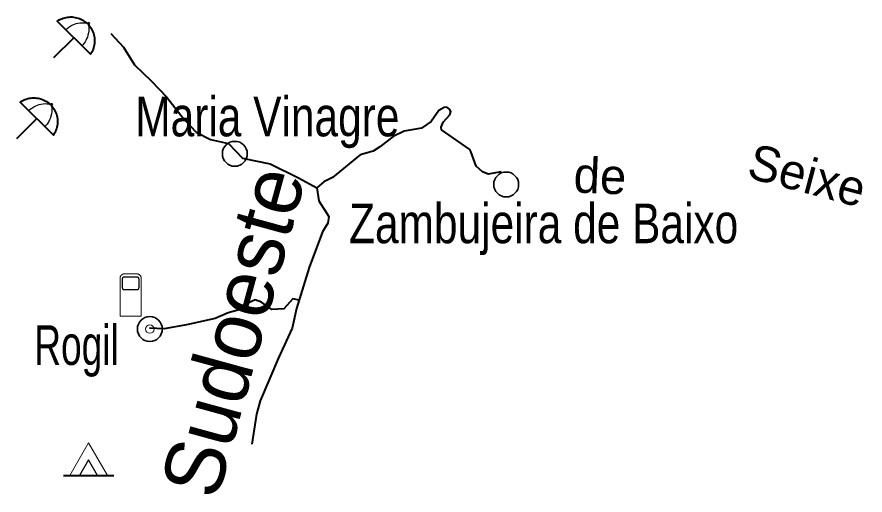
# Model space of a CAD drawing. Extents: x 515362 to 530328, y 4133002 to 4141437.
import ezdxf

# ---------------------------------------------------------------- set-up
doc = ezdxf.new("R2010")
doc.units = 0
doc.header["$LTSCALE"] = 280
for name, color, linetype in [('13', 7, 'Continuous'), ('14', 7, 'Continuous'), ('49', 7, 'Continuous'), ('59', 7, 'Continuous')]:
    doc.layers.add(name, color=color, linetype=linetype)
for name, color, linetype, lineweight in [('17', 7, 'Continuous', 35), ('23', 7, 'Continuous', 40), ('27', 7, 'Continuous', 13), ('57', 7, 'Continuous', 40)]:
    doc.layers.add(name, color=color, linetype=linetype, lineweight=lineweight)

msp = doc.modelspace()

# ---------------------------------------------------------------- linework, layer by layer
at = {"layer": '17'}
for centre in [(519206.5, 4139022.7), (523995.3, 4138481.4), (517706.9, 4135930.7)]:
    msp.add_circle(centre, 220, dxfattribs=at)
at = {"layer": '17', "lineweight": 13}
msp.add_circle((517706.9, 4135930.7), 75, dxfattribs=at)
at = {"layer": '23'}
for points in [[(517017.7, 4141142.4), (517244.1, 4140902.4), (517439.1, 4140592.9), (517738.5, 4140304.7), (518000.5, 4140029), (518319.4, 4139624), (518525.4, 4139403.4), (518776.8, 4139275.9), (519092.7, 4139204.6), (519343.5, 4138942.9), (519829.1, 4138844.6), (520332.8, 4138598.9), (520653.5, 4138424.5)], [(523905.1, 4138707), (523676.9, 4138665.7), (523577.7, 4138706.2), (523468.2, 4138805.2), (523373.4, 4139060.9), (523354, 4139096.2), (522853.9, 4139444), (522850.7, 4139490.4), (522885.3, 4139583.6), (523001.6, 4139710.3), (523017.4, 4139770.5), (522995.1, 4139813.2), (522946.2, 4139846.4), (522899.4, 4139840.5), (522807, 4139787.7), (522669.6, 4139592.5), (522503.7, 4139477.1), (522196.4, 4139423.2), (521998.3, 4139328.8), (521767.5, 4139142.8), (521645.6, 4139068.9), (521417, 4139005), (520932.5, 4138602.5), (520777.6, 4138528.5), (520653.5, 4138424.5)], [(520653.5, 4138424.5), (520691.9, 4138190.3), (520862.7, 4137918.6), (520845.2, 4137799.1), (520754, 4137643.9), (520517.2, 4137017.2)], [(520517.2, 4137017.2), (520296.8, 4136293.4), (520218.7, 4135947.6), (519975.8, 4135423.5), (519652, 4134662.9), (519586.4, 4134431.5), (519504.4, 4133899.3)], [(520340.5, 4136441), (520231.9, 4136463.1), (520068.9, 4136285.8), (519858.8, 4136278.4), (519677.6, 4136407.7), (519565.3, 4136448.3), (519413.2, 4136378.1), (519348, 4136285.8), (519090.8, 4136215.5), (518859, 4136115.8), (518355.4, 4136004.9), (517960.6, 4135934.7), (517703.4, 4135945.8)]]:
    msp.add_lwpolyline(points, dxfattribs=at)
at = {"layer": '27'}
msp.add_lwpolyline([(517260.9, 4136905.8), (517475.1, 4136905.8), (517479.6, 4136905.5), (517484.1, 4136905.2), (517488.4, 4136904.5), (517492.9, 4136903.8), (517497.1, 4136902.5), (517501.1, 4136901.2), (517505.1, 4136899.8), (517509.1, 4136898), (517512.9, 4136896), (517516.6, 4136893.8), (517520.1, 4136891.5), (517523.6, 4136889), (517526.9, 4136886.2), (517529.9, 4136883.2), (517532.9, 4136880.2), (517535.9, 4136877), (517538.4, 4136873.8), (517540.9, 4136870.2), (517543.4, 4136866.8), (517545.4, 4136863), (517547.4, 4136859.2), (517549.1, 4136855.5), (517550.6, 4136851.5), (517551.9, 4136847.2), (517552.9, 4136843.2), (517553.9, 4136839), (517554.4, 4136834.8), (517554.6, 4136830.5), (517554.9, 4136826), (517554.9, 4136155.8), (517181.1, 4136155.8), (517181.1, 4136826), (517181.4, 4136830.5), (517181.6, 4136834.8), (517182.1, 4136839), (517183.1, 4136843.2), (517184.1, 4136847.2), (517185.4, 4136851.5), (517186.9, 4136855.5), (517188.6, 4136859.2), (517190.6, 4136863), (517192.9, 4136866.8), (517195.1, 4136870.2), (517197.6, 4136873.8), (517200.1, 4136877), (517203.1, 4136880.2), (517206.1, 4136883.2), (517209.1, 4136886.2), (517212.4, 4136889), (517215.9, 4136891.5), (517219.4, 4136893.8), (517223.1, 4136896), (517226.9, 4136898), (517230.9, 4136899.8), (517234.9, 4136901.2), (517238.9, 4136902.5), (517243.1, 4136903.8), (517247.6, 4136904.5), (517251.9, 4136905.2), (517256.4, 4136905.5), (517260.9, 4136905.8)], close=True, dxfattribs=at)
at = {"layer": '27', "lineweight": 25}
msp.add_lwpolyline([(517256.4, 4136854.5), (517479.6, 4136854.5), (517483.4, 4136854.2), (517487.1, 4136853.2), (517490.9, 4136851.8), (517494.1, 4136849.5), (517497.4, 4136847), (517500.1, 4136844), (517502.9, 4136840.5), (517505.1, 4136836.8), (517506.9, 4136832.5), (517508.6, 4136828), (517509.6, 4136823.2), (517510.4, 4136818.2), (517510.6, 4136813), (517510.6, 4136662), (517510.4, 4136656.8), (517509.6, 4136651.8), (517508.6, 4136647), (517506.9, 4136642.5), (517505.1, 4136638.2), (517502.9, 4136634.2), (517500.1, 4136630.8), (517497.4, 4136627.8), (517494.1, 4136625.2), (517490.9, 4136623), (517487.1, 4136621.5), (517483.4, 4136620.5), (517479.6, 4136620.2), (517256.4, 4136620.2), (517252.6, 4136620.5), (517248.9, 4136621.5), (517245.1, 4136623), (517241.9, 4136625.2), (517238.6, 4136627.8), (517235.9, 4136630.8), (517233.1, 4136634.2), (517230.9, 4136638.2), (517229.1, 4136642.5), (517227.4, 4136647), (517226.4, 4136651.8), (517225.6, 4136656.8), (517225.4, 4136662), (517225.4, 4136813), (517225.6, 4136818.2), (517226.4, 4136823.2), (517227.4, 4136828), (517229.1, 4136832.5), (517230.9, 4136836.8), (517233.1, 4136840.5), (517235.9, 4136844), (517238.6, 4136847), (517241.9, 4136849.5), (517245.1, 4136851.8), (517248.9, 4136853.2), (517252.6, 4136854.2)], close=True, dxfattribs=at)
at = {"layer": '57'}
for p, q in [((516015.3, 4140720), (516365.5, 4141070.2)), ((515362, 4139293.1), (515712.2, 4139643.4)), ((516183.3, 4133348.9), (517069.2, 4133348.9))]:
    msp.add_line(p, q, dxfattribs=at)
for points in [[(516634.2, 4141339), (516623.5, 4141299), (516634, 4141287.1), (516650.3, 4141266.3), (516665.3, 4141244.6), (516678.9, 4141222), (516691, 4141198.6), (516701.7, 4141174.5), (516710.8, 4141149.7), (516718.3, 4141124.4), (516724.3, 4141098.7), (516728.6, 4141072.7), (516731.3, 4141046.4), (516732.3, 4141020.1), (516731.7, 4140993.7), (516729.4, 4140967.4), (516725.4, 4140941.3), (516719.9, 4140915.5), (516712.7, 4140890.1), (516703.9, 4140865.2), (516693.6, 4140841), (516681.8, 4140817.4), (516668.5, 4140794.6), (516657.7, 4140778.1), (516073.4, 4141362.4), (516084.7, 4141370), (516107.3, 4141383.6), (516130.7, 4141395.7), (516154.9, 4141406.4), (516179.6, 4141415.5), (516204.9, 4141423), (516230.6, 4141429), (516256.6, 4141433.3), (516282.9, 4141436), (516309.2, 4141437), (516335.6, 4141436.4), (516361.9, 4141434.1), (516388, 4141430.1), (516413.8, 4141424.6), (516439.2, 4141417.4), (516464.1, 4141408.6), (516488.4, 4141398.3), (516512, 4141386.5), (516534.8, 4141373.2), (516556.7, 4141358.6), (516577.7, 4141342.6), (516594.3, 4141328.2)], [(515980.9, 4139912.1), (515970.2, 4139872.1), (515980.6, 4139860.2), (515996.9, 4139839.5), (516011.9, 4139817.8), (516025.5, 4139795.1), (516037.7, 4139771.7), (516048.3, 4139747.6), (516057.4, 4139722.8), (516065, 4139697.5), (516070.9, 4139671.8), (516075.2, 4139645.8), (516077.9, 4139619.6), (516078.9, 4139593.2), (516078.3, 4139566.8), (516076, 4139540.5), (516072.1, 4139514.4), (516066.5, 4139488.6), (516059.3, 4139463.2), (516050.6, 4139438.4), (516040.3, 4139414.1), (516028.5, 4139390.5), (516015.2, 4139367.7), (516004.4, 4139351.2), (515420, 4139935.5), (515431.3, 4139943.1), (515453.9, 4139956.7), (515477.4, 4139968.9), (515501.5, 4139979.5), (515526.3, 4139988.6), (515551.5, 4139996.2), (515577.2, 4140002.1), (515603.3, 4140006.4), (515629.5, 4140009.1), (515655.9, 4140010.1), (515682.3, 4140009.5), (515708.6, 4140007.2), (515734.7, 4140003.2), (515760.4, 4139997.7), (515785.8, 4139990.5), (515810.7, 4139981.8), (515835, 4139971.5), (515858.6, 4139959.6), (515881.4, 4139946.4), (515903.3, 4139931.7), (515924.3, 4139915.7), (515941, 4139901.4)]]:
    msp.add_lwpolyline(points, close=True, dxfattribs=at)
at = {"layer": '57', "lineweight": 13}
for points in [[(516703.9, 4140865.2), (516693.6, 4140841), (516681.8, 4140817.4), (516668.5, 4140794.6), (516657.7, 4140778.1), (516073.4, 4141362.4), (516084.7, 4141370), (516107.3, 4141383.6), (516130.7, 4141395.7), (516154.9, 4141406.4), (516179.6, 4141415.5), (516204.9, 4141423), (516230.6, 4141429), (516256.6, 4141433.3), (516282.9, 4141436), (516309.2, 4141437), (516335.6, 4141436.4), (516361.9, 4141434.1), (516388, 4141430.1), (516413.8, 4141424.6), (516439.2, 4141417.4), (516464.1, 4141408.6), (516488.4, 4141398.3), (516512, 4141386.5), (516534.8, 4141373.2), (516556.7, 4141358.6), (516577.7, 4141342.6), (516594.3, 4141328.2), (516634.2, 4141339), (516623.5, 4141299), (516634, 4141287.1), (516650.3, 4141266.3), (516665.3, 4141244.6), (516678.9, 4141222), (516691, 4141198.6), (516701.7, 4141174.5), (516710.8, 4141149.7), (516718.3, 4141124.4), (516724.3, 4141098.7), (516728.6, 4141072.7), (516731.3, 4141046.4), (516732.3, 4141020.1), (516731.7, 4140993.7), (516729.4, 4140967.4), (516725.4, 4140941.3), (516719.9, 4140915.5), (516712.7, 4140890.1)], [(516050.6, 4139438.4), (516040.3, 4139414.1), (516028.5, 4139390.5), (516015.2, 4139367.7), (516004.4, 4139351.2), (515420, 4139935.5), (515431.3, 4139943.1), (515453.9, 4139956.7), (515477.4, 4139968.9), (515501.5, 4139979.5), (515526.3, 4139988.6), (515551.5, 4139996.2), (515577.2, 4140002.1), (515603.3, 4140006.4), (515629.5, 4140009.1), (515655.9, 4140010.1), (515682.3, 4140009.5), (515708.6, 4140007.2), (515734.7, 4140003.2), (515760.4, 4139997.7), (515785.8, 4139990.5), (515810.7, 4139981.8), (515835, 4139971.5), (515858.6, 4139959.6), (515881.4, 4139946.4), (515903.3, 4139931.7), (515924.3, 4139915.7), (515941, 4139901.4), (515980.9, 4139912.1), (515970.2, 4139872.1), (515980.6, 4139860.2), (515996.9, 4139839.5), (516011.9, 4139817.8), (516025.5, 4139795.1), (516037.7, 4139771.7), (516048.3, 4139747.6), (516057.4, 4139722.8), (516065, 4139697.5), (516070.9, 4139671.8), (516075.2, 4139645.8), (516077.9, 4139619.6), (516078.9, 4139593.2), (516078.3, 4139566.8), (516076, 4139540.5), (516072.1, 4139514.4), (516066.5, 4139488.6), (516059.3, 4139463.2)], [(516294.9, 4133348.9), (516626.3, 4133922.6), (516957.6, 4133348.9), (516737.9, 4133348.9)]]:
    msp.add_lwpolyline(points, close=True, dxfattribs=at)
at = {"layer": '57', "lineweight": 25}
for points in [[(516224.1, 4141211.7), (516249.5, 4141235), (516276.9, 4141256.4), (516315, 4141280.6), (516347.3, 4141297), (516374.9, 4141308.4), (516407.5, 4141319), (516438.2, 4141326.4), (516475.6, 4141332.2), (516511.8, 4141334.6), (516545.4, 4141334), (516578.6, 4141330.7), (516594.3, 4141328.2), (516623.5, 4141299), (516625.5, 4141287.1), (516628.8, 4141257.2), (516630, 4141225.8), (516628.3, 4141187.9), (516624, 4141155.1), (516615.3, 4141115.6), (516604.5, 4141081.6), (516592, 4141051.4), (516576.8, 4141021.2), (516564.2, 4141000.2), (516545.7, 4140973.5), (516527.4, 4140950.7), (516507, 4140928.8)], [(515570.8, 4139784.8), (515596.1, 4139808.2), (515623.6, 4139829.6), (515661.7, 4139853.8), (515693.9, 4139870.1), (515721.6, 4139881.6), (515754.2, 4139892.1), (515784.9, 4139899.5), (515822.2, 4139905.3), (515858.4, 4139907.7), (515892, 4139907.1), (515925.3, 4139903.8), (515941, 4139901.4), (515970.2, 4139872.1), (515972.1, 4139860.2), (515975.4, 4139830.4), (515976.6, 4139799), (515974.9, 4139761), (515970.6, 4139728.3), (515961.9, 4139688.8), (515951.1, 4139654.8), (515938.7, 4139624.5), (515923.5, 4139594.4), (515910.9, 4139573.3), (515892.4, 4139546.6), (515874, 4139523.9), (515853.6, 4139501.9)], [(516626.3, 4133622.7), (516468.1, 4133348.9), (516784.4, 4133348.9)]]:
    msp.add_lwpolyline(points, close=True, dxfattribs=at)

# ---------------------------------------------------------------- texts
at = {"layer": '13', "width": 0.7}
msp.add_text('Rogil', height=700, dxfattribs=at).set_placement((515666.5, 4135297.5))
at = {"layer": '14', "width": 0.8}
for s, p in [('Maria Vinagre', (517450.2, 4139331.3)), ('Zambujeira de Baixo', (521222.5, 4137445.7))]:
    msp.add_text(s, height=700, dxfattribs=at).set_placement(p)
at = {"layer": '49'}
msp.add_text('Sudoeste', height=1050, rotation=74.673, dxfattribs=at).set_placement((518895.2, 4132890.5))
at = {"layer": '59'}
for s, rotation, p in [('Seixe', 345.151, (528217.8, 4138609)), ('de', 357.606, (525175.3, 4138342.8))]:
    msp.add_text(s, height=625, rotation=rotation, dxfattribs=at).set_placement(p)

doc.saveas('drawing.dxf')
